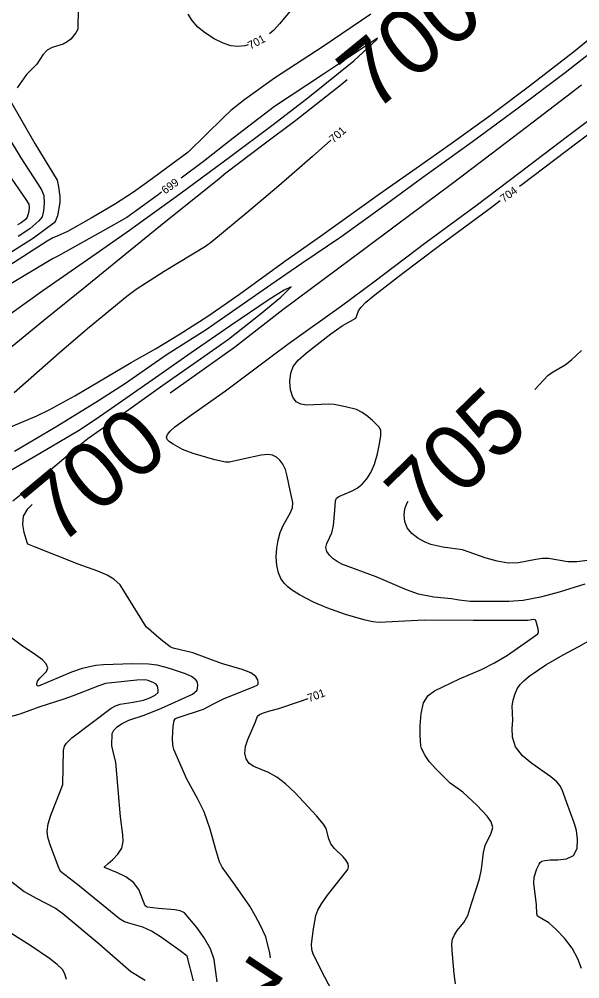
# Model space of a CAD drawing. Extents: x -291892836 to 2945206, y -477993085 to 1832792.
# Drawn here: x 1852457.2 to 1852737.2, y 544304.4 to 544783.9 of the extents above; entities that cross this region are included whole.
import ezdxf

# ---------------------------------------------------------------- set-up
doc = ezdxf.new("R2010")
doc.units = 0
for name, color, linetype in [('DT_X_Contour_Minor', 7, 'Continuous'), ('DT_X_Terrain_Ground_Line', 7, 'Continuous'), ('Level 19', 7, 'Continuous')]:
    doc.layers.add(name, color=color, linetype=linetype)

msp = doc.modelspace()

# ---------------------------------------------------------------- linework, layer by layer
at = {"layer": 'DT_X_Contour_Minor'}
for points in [[(1852486.77, 544789.45), (1852486.49, 544779), (1852485.59, 544777.02), (1852482.96, 544773.94), (1852481.26, 544772.57), (1852479.13, 544771.46), (1852473.71, 544769.76), (1852471.13, 544768.35), (1852469.08, 544766.15), (1852466, 544761.36), (1852462.9, 544758.33), (1852460.94, 544756.27), (1852456.24, 544749.55)], [(1852595.04, 544790.85), (1852587.27, 544781.58), (1852584.4, 544778.43), (1852582.32, 544776.52)], [(1852632.85, 544786.49), (1852609.04, 544770.24), (1852584.79, 544754.39), (1852569.89, 544743.73), (1852562.85, 544738.21), (1852559.21, 544734.85), (1852541.68, 544717.45), (1852523.76, 544704.25), (1852514.37, 544697.51), (1852505.33, 544691.61), (1852493.24, 544684.42), (1852481.4, 544677.83), (1852476.18, 544675.48), (1852474.12, 544674.63), (1852471.22, 544673.07), (1852449.68, 544659.16)], [(1852571.59, 544771.14), (1852569.93, 544770.66), (1852566.51, 544770.28), (1852562.97, 544770.65), (1852559.05, 544771.9), (1852554.65, 544774.05), (1852550.22, 544776.86), (1852546.39, 544780), (1852543.6, 544783.19), (1852541.67, 544786.42)], [(1852451.02, 544579.33), (1852466.01, 544585.74), (1852472.18, 544588.67), (1852485.03, 544595.72), (1852513.12, 544612.32), (1852525.3, 544619.28), (1852537.71, 544626.68), (1852551.43, 544635.49), (1852567.18, 544646.54), (1852589.87, 544662.96), (1852607.69, 544675.53), (1852637.14, 544696.68), (1852655.52, 544709.43), (1852673.03, 544721.76), (1852692.57, 544736.03), (1852712.15, 544750.61), (1852734.02, 544767.66), (1852753.82, 544783.74)], [(1852447.15, 544632.67), (1852469.02, 544648.28), (1852495.68, 544666.89), (1852512.3, 544678.42), (1852537.46, 544696.6), (1852562.9, 544715.51), (1852583.45, 544730.73), (1852601.32, 544744.58), (1852624.28, 544763.15), (1852635.77, 544773.69), (1852636.18, 544774.37), (1852632.12, 544771.78), (1852609.14, 544756.41), (1852584.71, 544740.24), (1852564.05, 544724.43), (1852549.35, 544712.78), (1852538.06, 544704.52)], [(1852740.71, 544765.56), (1852729.86, 544757.1), (1852706.37, 544739.39), (1852683.66, 544722.68), (1852658.82, 544704.81), (1852638.15, 544689.69), (1852617.91, 544674.99), (1852598.32, 544661.79), (1852582.99, 544651.26), (1852558.35, 544633.95), (1852550.63, 544628.76), (1852531.12, 544616.38), (1852509.76, 544601.62), (1852495.53, 544592.38), (1852475.14, 544579.82), (1852454.97, 544567.95)], [(1852392.45, 544573.22), (1852407.74, 544585.55), (1852434.1, 544604.97), (1852446.04, 544614.4), (1852469.47, 544633.49), (1852490.97, 544650.93), (1852509.94, 544666.29), (1852527.77, 544680.8), (1852557.05, 544704.36), (1852560.5, 544707.13), (1852579.65, 544721.55), (1852595.38, 544733.42), (1852618.01, 544751.33), (1852621.05, 544753.75)], [(1852532.58, 544597.22), (1852543.39, 544604.8), (1852564.76, 544620.09), (1852588.9, 544638.89), (1852602.55, 544649.06), (1852628.53, 544668.33), (1852646.35, 544681.64), (1852672.92, 544701.43), (1852692.96, 544716.68), (1852713.96, 544732.7), (1852738.11, 544751.19)], [(1852452.68, 544743.36), (1852465.07, 544721.81), (1852476.25, 544703.52), (1852476.93, 544700.11), (1852477.5, 544695.37), (1852477.47, 544692.28), (1852476.33, 544685.59), (1852475.4, 544683.08), (1852474.69, 544682.21), (1852464.45, 544674.5), (1852453.1, 544667.34)], [(1852657.57, 544425.93), (1852657.55, 544431.08), (1852657.95, 544437.06), (1852659.2, 544442.41), (1852661.55, 544446.03), (1852664.58, 544448.25), (1852677.19, 544454.28), (1852688.17, 544458.99), (1852694.62, 544462.26), (1852701.04, 544466.17), (1852711.05, 544473.2), (1852716.21, 544476.88), (1852716.51, 544477.87), (1852716.4, 544479.35), (1852715.27, 544483.4), (1852715, 544483.84), (1852714.04, 544483.89), (1852711.23, 544483.42), (1852683.95, 544483.49), (1852659.48, 544483.7), (1852637, 544482.48), (1852633.89, 544482.81), (1852629.95, 544483.56), (1852620.14, 544486.42), (1852610.94, 544489.78), (1852604.18, 544492.68), (1852597.2, 544496.31), (1852593.24, 544498.86), (1852591.35, 544500.37), (1852589.54, 544502.14), (1852587.93, 544504.38), (1852586.69, 544507.3), (1852585.92, 544511.02), (1852585.64, 544515.24), (1852585.84, 544519.56), (1852586.52, 544523.65), (1852587.63, 544527.45), (1852589.13, 544530.93), (1852592.57, 544537.06), (1852593.65, 544539.82), (1852593.84, 544542.5), (1852592.62, 544548.37), (1852591.13, 544555.56), (1852590.18, 544558.9), (1852588.91, 544561.58), (1852587.37, 544563.61), (1852585.66, 544565.07), (1852583.76, 544566.01), (1852581.34, 544566.39), (1852578.02, 544566.14), (1852568.88, 544564.12), (1852562.21, 544562.55), (1852560.29, 544562.51), (1852554.88, 544563.77), (1852544.09, 544566.94), (1852538.84, 544568.95), (1852534.07, 544571.52), (1852532.27, 544572.81), (1852531.17, 544573.98), (1852530.85, 544575.14), (1852531.34, 544576.46), (1852532.7, 544578.1), (1852535.02, 544580.17), (1852542.8, 544585.91), (1852560.27, 544598.17), (1852583.6, 544615.69), (1852592.09, 544621.96), (1852618.19, 544640.65), (1852634.32, 544652.75), (1852660.5, 544672.49), (1852685.4, 544690.86), (1852707.36, 544707.42), (1852731.09, 544725.39), (1852750.62, 544740.17)], [(1852707.07, 544700.46), (1852708.19, 544701.3), (1852735.79, 544722.11), (1852759.11, 544739.68)], [(1852451.66, 544725.1), (1852458.06, 544714.66), (1852466.41, 544701.89), (1852468.43, 544698.68), (1852469.48, 544695.74), (1852469.79, 544692.03), (1852469.45, 544688.18), (1852468.73, 544685.1), (1852466.97, 544683.17), (1852462.62, 544679.19), (1852456.72, 544675.41)], [(1852612.95, 544723.43), (1852603.64, 544715.28), (1852586.88, 544700.63), (1852570.84, 544687.23), (1852553.51, 544672.6), (1852550.35, 544670.36), (1852529.65, 544657.77), (1852515.71, 544648.84), (1852510.98, 544645.3), (1852491.41, 544629.14), (1852477.25, 544617.12), (1852454.69, 544597.29)], [(1852453.24, 544704.46), (1852460.61, 544693.84), (1852462.03, 544691.41), (1852462.29, 544690.03), (1852461.99, 544687.84), (1852461.19, 544685.05), (1852460.37, 544683.86), (1852458.21, 544682.13), (1852456.44, 544681.11)], [(1852528.37, 544697.45), (1852526.6, 544696.15), (1852511, 544684.85), (1852499.21, 544678.08), (1852476.53, 544665.44), (1852473.9, 544664.11), (1852453.13, 544651.73)], [(1852739.76, 544501.57), (1852726.95, 544497.58), (1852717.6, 544495.18), (1852708.9, 544493.52), (1852701.83, 544493.02), (1852682.47, 544492.91), (1852676.9, 544493.71), (1852673.15, 544494.36), (1852664.38, 544495.19), (1852656.72, 544496.66), (1852650.64, 544498.76), (1852635.56, 544505.35), (1852618.33, 544511.68), (1852615.97, 544512.92), (1852613.97, 544514.33), (1852612.17, 544516.04), (1852610.85, 544517.95), (1852610.36, 544519.95), (1852610.93, 544521.98), (1852613.41, 544527.21), (1852614.27, 544530.91), (1852614.94, 544538.51), (1852615.19, 544543.22), (1852615.73, 544544.53), (1852616.83, 544545.41), (1852623.22, 544548.05), (1852625.96, 544549.61), (1852628.59, 544551.63), (1852630.9, 544554.19), (1852632.89, 544557.46), (1852634.62, 544561.62), (1852636.11, 544566.66), (1852637.25, 544571.76), (1852637.89, 544575.91), (1852637.9, 544578.42), (1852637.24, 544579.88), (1852633.86, 544583.21), (1852631.35, 544585.45), (1852628.58, 544587.45), (1852625.74, 544588.81), (1852620.14, 544590.27), (1852614.59, 544591.35), (1852611.47, 544591.56), (1852600.84, 544591.07), (1852597.91, 544591.48), (1852595.57, 544592.7), (1852593.85, 544595.04), (1852592.8, 544598.65), (1852592.46, 544602.9), (1852592.86, 544606.98), (1852594.11, 544610.34), (1852596.56, 544613.49), (1852600.64, 544617.18), (1852612.89, 544626.73), (1852618.52, 544630.67), (1852625.34, 544634.49), (1852625.77, 544635.38), (1852626.61, 544638.12), (1852627.86, 544639.93), (1852630.4, 544642.46), (1852634.85, 544646.22), (1852648.75, 544657.04), (1852666.51, 544670.36), (1852692.44, 544689.44), (1852697.48, 544693.24)], [(1852463.29, 544550.58), (1852488.21, 544571.71), (1852491.51, 544574.33), (1852503.77, 544583.07), (1852529.05, 544600.99), (1852547.84, 544614.13), (1852561.73, 544624), (1852577.63, 544636.55), (1852587.89, 544645.09), (1852593.08, 544650.25), (1852589.53, 544648.46), (1852582.11, 544643.92), (1852562.93, 544630.82), (1852543.1, 544617.16), (1852523.72, 544603.58), (1852495.61, 544584.03), (1852486.9, 544578.27), (1852468.18, 544567.28), (1852442.94, 544552.57)], [(1852714.71, 544598.93), (1852714.84, 544599.04), (1852721.19, 544605.95), (1852723.64, 544607.55), (1852729.88, 544611.15), (1852733.11, 544613.67), (1852738.06, 544618.45)], [(1852454.13, 544543.24), (1852463.29, 544550.58)], [(1852582.71, 544314.89), (1852582.46, 544317.33), (1852580.35, 544325.34), (1852577.58, 544331.42), (1852575.32, 544335.75), (1852572.37, 544340.72), (1852565.08, 544351.18), (1852558.68, 544360.2), (1852557.34, 544362.85), (1852555.33, 544369.48), (1852552.66, 544379.21), (1852549.57, 544387.79), (1852546.31, 544394.48), (1852540.95, 544404.24), (1852534.43, 544419.04), (1852533.97, 544421.39), (1852533.85, 544424.48), (1852534.2, 544430.64), (1852534.67, 544433.56), (1852535.38, 544434.49), (1852536.62, 544435.05), (1852549.22, 544439.19), (1852554.6, 544441.97), (1852559.29, 544444.32), (1852574.63, 544450.43), (1852576.09, 544451.12), (1852576.6, 544451.65), (1852576.62, 544452.43), (1852576.4, 544453.75), (1852575.41, 544455.45), (1852572.93, 544457.26), (1852568.57, 544458.96), (1852558.24, 544462.02), (1852543.97, 544467.36), (1852534.11, 544469.66), (1852532.6, 544470.35), (1852528.21, 544473.78), (1852520.61, 544480.29), (1852507.73, 544501.34), (1852504.57, 544504.14), (1852501.23, 544506.14), (1852496.44, 544508.05), (1852486.72, 544511.62), (1852464.89, 544520.25), (1852461.58, 544521.65), (1852461.18, 544522.49), (1852459.66, 544527.44), (1852459.02, 544531.41), (1852459.47, 544535.53), (1852461.58, 544539.25), (1852463.66, 544541.35)], [(1852741.01, 544513.52), (1852735.68, 544512.72), (1852731.27, 544512.79), (1852721.65, 544514.51), (1852718.61, 544514.47), (1852715.2, 544513.97), (1852706.63, 544512.31), (1852701.47, 544512.19), (1852695.87, 544513.12), (1852690.45, 544514.68), (1852678.63, 544518.77), (1852668.87, 544520.1), (1852662.78, 544521.52), (1852659.64, 544522.78), (1852656.37, 544524.61), (1852653.33, 544526.97), (1852651.01, 544529.79), (1852649.77, 544532.96), (1852649.48, 544536.22), (1852649.91, 544539.29), (1852650.85, 544541.95), (1852651.54, 544543.11)], [(1852738.06, 544309.52), (1852736.18, 544314.42), (1852733.38, 544319.69), (1852729.6, 544324.77), (1852725.46, 544329.16), (1852721.68, 544332.4), (1852716.04, 544335.82), (1852715.68, 544336.97), (1852715.54, 544341.41), (1852714.3, 544352.29), (1852714.49, 544355.26), (1852715.69, 544359.37), (1852716.86, 544361.76), (1852717.48, 544362.55), (1852718.33, 544363.19), (1852719.8, 544363.63), (1852722.38, 544363.82), (1852726.27, 544363.83), (1852730.56, 544364.31), (1852734.04, 544366.04), (1852735.82, 544369.51), (1852736.14, 544374.02), (1852735.53, 544378.56), (1852734.47, 544382.39), (1852730.72, 544392.36), (1852728.44, 544398.79), (1852727.16, 544401.08), (1852725.78, 544402.78), (1852722.81, 544405.28), (1852713.23, 544411.97), (1852708.6, 544415.92), (1852705.06, 544420.41), (1852703.57, 544425.14), (1852703.5, 544429.66), (1852703.82, 544433.49), (1852703.39, 544440.91), (1852703.86, 544443.65), (1852704.79, 544446.57), (1852705.99, 544449.26), (1852707.36, 544451.43), (1852709.21, 544453.4), (1852711.93, 544455.62), (1852720.26, 544461.37), (1852728.87, 544466.36), (1852736.69, 544470.4), (1852750.94, 544478.46)], [(1852556.07, 544303.01), (1852554.61, 544314.1), (1852552.74, 544319.4), (1852549.56, 544324.98), (1852545.87, 544330.12), (1852539.79, 544337.39), (1852539.07, 544337.81), (1852537.61, 544338.33), (1852535.01, 544338.86), (1852526.82, 544339.64), (1852521.11, 544340.18), (1852520.11, 544340.89), (1852516.94, 544349.09), (1852514.27, 544352.6), (1852510.43, 544355.4), (1852506.25, 544357.41), (1852499.82, 544360.08), (1852499.92, 544360.47), (1852501.72, 544362.1), (1852503.96, 544364.04), (1852506.48, 544366.67), (1852508.43, 544369.73), (1852509.17, 544373.02), (1852509.03, 544376.34), (1852507.85, 544385.33), (1852505.52, 544412.77), (1852504.24, 544417.88), (1852503.53, 544421.02), (1852503.67, 544426.98), (1852504.49, 544428.72), (1852506.15, 544430.41), (1852508.28, 544431.9), (1852511.94, 544433.7), (1852519.67, 544436.25), (1852528.36, 544439.61), (1852543.83, 544446.6), (1852545.89, 544448.5), (1852546.33, 544449.5), (1852546.39, 544451.36), (1852546.05, 544452.96), (1852545.51, 544453.77), (1852543.29, 544455.48), (1852540.24, 544456.79), (1852533.38, 544459.1), (1852530.01, 544460.21), (1852526.1, 544461.14), (1852521.77, 544461.67), (1852513.83, 544461.86), (1852499.39, 544461.32), (1852495.47, 544460.94), (1852488.7, 544459.45), (1852483.3, 544457.61), (1852466.92, 544450.6), (1852466.21, 544450.84), (1852466.01, 544451.72), (1852466.43, 544453.08), (1852467.53, 544454.68), (1852470.85, 544458.01), (1852471.57, 544459.84), (1852470.79, 544461.85), (1852468.91, 544463.87), (1852464.23, 544467.2), (1852458.82, 544470.65), (1852451.61, 544476.22)], [(1852544.22, 544303.39), (1852541.18, 544315.71), (1852537.66, 544318.4), (1852528.35, 544325.1), (1852523.25, 544328.27), (1852519.02, 544330.25), (1852513.18, 544331.84), (1852509.8, 544332.91), (1852507.35, 544334.47), (1852486.51, 544351.35), (1852477.87, 544357.98), (1852476.62, 544360.7), (1852472.56, 544371.95), (1852471.57, 544375.22), (1852471.2, 544378.27), (1852471.64, 544381.82), (1852472.99, 544386.29), (1852477.4, 544397.24), (1852479, 544401.45), (1852479.31, 544418.6), (1852479.93, 544420.67), (1852480.85, 544422.2), (1852483.57, 544424.81), (1852503.13, 544439.68), (1852505.26, 544440.8), (1852507.73, 544441.61), (1852514.11, 544442.74), (1852519.34, 544443.66), (1852522.45, 544444.75), (1852525.14, 544446.1), (1852526.6, 544447.43), (1852526.71, 544448.84), (1852526.29, 544450.66), (1852525.63, 544451.58), (1852524.51, 544452.4), (1852521.57, 544453.53), (1852520.1, 544453.78), (1852516.02, 544453.65), (1852500.41, 544452.02), (1852496.96, 544450.85), (1852484.15, 544445.9), (1852479.5, 544444.14), (1852467.54, 544440.35), (1852457.5, 544436.71), (1852443.51, 544432.86)], [(1852620.84, 544284.21), (1852609.93, 544305.29), (1852603.99, 544316.71), (1852603.33, 544319.06), (1852603.26, 544321.76), (1852604.28, 544329.41), (1852605.45, 544336.09), (1852606.33, 544338.77), (1852608.13, 544341.97), (1852611.18, 544346.19), (1852621.44, 544359.06), (1852621.77, 544360.4), (1852621.47, 544361.9), (1852620.56, 544363.61), (1852619.01, 544365.46), (1852614.66, 544369.51), (1852612.85, 544371.83), (1852611.84, 544374.38), (1852610.54, 544379.52), (1852609.29, 544381.76), (1852605.71, 544385.85), (1852595.05, 544397.34), (1852590.29, 544401.78), (1852585.88, 544405.18), (1852581.74, 544407.46), (1852574.34, 544410.47), (1852572.15, 544412.1), (1852570.66, 544414.36), (1852569.99, 544417.19), (1852570.25, 544420.45), (1852571.41, 544423.98), (1852575.29, 544432.8), (1852576.32, 544435.67), (1852577.18, 544436.48), (1852579.25, 544437.41), (1852582.39, 544438.32), (1852586.92, 544439.55), (1852597.25, 544442.98), (1852601.48, 544444.56)], [(1852675.15, 544301.98), (1852674.48, 544306.92), (1852673.4, 544318.64), (1852673.37, 544321.74), (1852673.71, 544324.23), (1852674.57, 544326.41), (1852675.99, 544328.52), (1852679.29, 544332.56), (1852681.3, 544336.03), (1852682.32, 544339.35), (1852683.38, 544343.02), (1852687.04, 544354.36), (1852688.15, 544359.19), (1852689.1, 544367.52), (1852689.89, 544371.04), (1852692.99, 544377.17), (1852693.72, 544380.02), (1852692.96, 544382.86), (1852691.01, 544385.68), (1852685.71, 544391.16), (1852678.75, 544397.65), (1852672.48, 544402.15), (1852665.26, 544409.37), (1852662.02, 544413.08), (1852659.92, 544415.94), (1852658.22, 544419.52), (1852657.9, 544420.82), (1852657.57, 544425.93)], [(1852452.75, 544353.53), (1852459.67, 544348.09), (1852465.72, 544344.77), (1852475.45, 544339.73), (1852479.08, 544337.03), (1852497.23, 544321.85), (1852512.97, 544308.15), (1852520.23, 544303.73)], [(1852480.89, 544304.15), (1852480.06, 544306.91), (1852478.85, 544309.03), (1852476.25, 544311.61), (1852472.32, 544314.54), (1852462.58, 544321.18), (1852449.11, 544329.8)]]:
    msp.add_lwpolyline(points, dxfattribs=at)

# ---------------------------------------------------------------- texts
at = {"layer": 'DT_X_Terrain_Ground_Line'}
for s, rotation, p in [('700', 39.2419, (1852634.09, 544736.78)), ('705', 44.2438, (1852660.37, 544527.53)), ('700', 39.8206, (1852476.95, 544520.1)), ('700', 326.4198, (1852552.06, 544289.62))]:
    msp.add_text(s, height=33, rotation=rotation, dxfattribs=at).set_placement(p)
at = {"layer": 'Level 19'}
for s, rotation, p in [('701', 28.2927, (1852572.77, 544768.65)), ('701', 41.1785, (1852614.16, 544721.83)), ('699', 36.1594, (1852530.15, 544696.27)), ('704', 36.9844, (1852699.31, 544692.12)), ('701', 20.4775, (1852602.05, 544442.64))]:
    msp.add_text(s, height=4, rotation=rotation, dxfattribs=at).set_placement(p)

doc.saveas('drawing.dxf')
